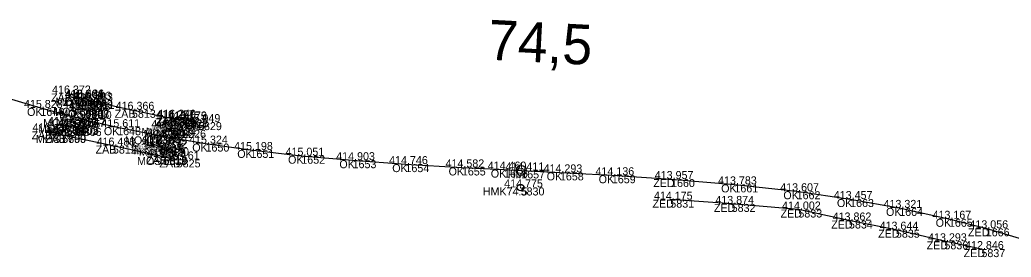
# Model space of a CAD drawing. Extents: x -621782 to -610392, y -1141853 to -1122321.
# Drawn here: x -619315.9 to -619167.3, y -1130096 to -1130060.4 of the extents above; entities that cross this region are included whole.
import ezdxf

# ---------------------------------------------------------------- set-up
doc = ezdxf.new("R2010")
doc.units = 0
for name, color, linetype in [('Vrstva 1', 7, 'Continuous'), ('Vrstva 13', 7, 'Continuous'), ('Vrstva 17', 7, 'Continuous'), ('Vrstva 18', 7, 'Continuous'), ('Vrstva 60', 7, 'Continuous'), ('Vrstva 61', 7, 'Continuous'), ('Vrstva 62', 7, 'Continuous'), ('Vrstva 7', 7, 'Continuous')]:
    doc.layers.add(name, color=color, linetype=linetype)

msp = doc.modelspace()

# ---------------------------------------------------------------- linework, layer by layer
at = {"layer": 'Vrstva 1'}
msp.add_lwpolyline([(-619320.09, -1130071.43), (-619312.85, -1130073.62), (-619306.69, -1130075.26), (-619301.33, -1130076.51), (-619294.43, -1130077.88), (-619288.08, -1130078.97), (-619281.34, -1130079.93), (-619273.72, -1130080.79), (-619266.03, -1130081.46), (-619258.1, -1130082.05), (-619249.64, -1130082.54), (-619243.32, -1130082.87), (-619240.74, -1130083), (-619234.94, -1130083.29), (-619227.15, -1130083.72), (-619218.27, -1130084.29), (-619208.77, -1130085.09), (-619199.44, -1130086.12), (-619191.42, -1130087.29), (-619184.06, -1130088.62), (-619176.61, -1130090.25), (-619171.08, -1130091.68), (-619164.55, -1130093.59)], dxfattribs=at)
at = {"layer": 'Vrstva 13'}
msp.add_lwpolyline([(-619171.73, -1130094.8), (-619177.28, -1130093.63), (-619184.55, -1130091.89), (-619191.59, -1130090.51), (-619199.18, -1130088.86), (-619209.18, -1130088.02), (-619218.38, -1130087.38)], dxfattribs=at)
at = {"layer": 'Vrstva 17'}
for points in [[(-619308.64, -1130071.46), (-619306.75, -1130072.12), (-619305.54, -1130072.39), (-619305.32, -1130072.57), (-619299.11, -1130073.9), (-619293.05, -1130075.18), (-619292.86, -1130075.09), (-619291.25, -1130075.42), (-619289.21, -1130075.75)], [(-619311.57, -1130077.13), (-619309.55, -1130077.66), (-619301.97, -1130079.27), (-619294.38, -1130080.89), (-619292.4, -1130081.34)]]:
    msp.add_lwpolyline(points, dxfattribs=at)
at = {"layer": 'Vrstva 18'}
for points in [[(-619309.59, -1130077.66), (-619309.26, -1130076.16), (-619307.78, -1130076.49), (-619307.65, -1130076.36), (-619307.23, -1130076.63), (-619305.73, -1130074.07), (-619306.1, -1130073.97), (-619306.07, -1130073.84), (-619306.98, -1130073.6), (-619306.65, -1130072.06)], [(-619294.4, -1130080.99), (-619294.13, -1130079.59), (-619294.94, -1130079.39), (-619294.83, -1130079.17), (-619295.25, -1130078.93), (-619293.76, -1130076.64), (-619293.36, -1130076.93), (-619293.09, -1130076.58), (-619291.58, -1130076.9), (-619291.22, -1130075.34)]]:
    msp.add_lwpolyline(points, dxfattribs=at)
at = {"layer": 'Vrstva 60'}
for p, q in [((-619308.64, -1130071.46), (-619308.64, -1130071.46)), ((-619306.75, -1130072.12), (-619306.75, -1130072.12)), ((-619306.65, -1130072.06), (-619306.65, -1130072.06)), ((-619305.54, -1130072.39), (-619305.54, -1130072.39)), ((-619312.85, -1130073.62), (-619312.85, -1130073.62)), ((-619306.98, -1130073.6), (-619306.98, -1130073.6)), ((-619306.07, -1130073.84), (-619306.07, -1130073.84)), ((-619305.32, -1130072.57), (-619305.32, -1130072.57)), ((-619299.11, -1130073.9), (-619299.11, -1130073.9)), ((-619306.69, -1130075.26), (-619306.69, -1130075.26)), ((-619306.1, -1130073.97), (-619306.1, -1130073.97)), ((-619305.73, -1130074.07), (-619305.73, -1130074.07)), ((-619293.05, -1130075.18), (-619293.05, -1130075.18)), ((-619292.86, -1130075.09), (-619292.86, -1130075.09)), ((-619291.22, -1130075.34), (-619291.22, -1130075.34)), ((-619309.26, -1130076.16), (-619309.26, -1130076.16)), ((-619307.78, -1130076.49), (-619307.78, -1130076.49)), ((-619307.65, -1130076.36), (-619307.65, -1130076.36)), ((-619307.23, -1130076.63), (-619307.23, -1130076.63)), ((-619301.33, -1130076.51), (-619301.33, -1130076.51)), ((-619293.76, -1130076.64), (-619293.76, -1130076.64)), ((-619293.09, -1130076.58), (-619293.09, -1130076.58)), ((-619291.25, -1130075.42), (-619291.25, -1130075.42)), ((-619289.21, -1130075.75), (-619289.21, -1130075.75)), ((-619311.57, -1130077.13), (-619311.57, -1130077.13)), ((-619309.59, -1130077.66), (-619309.59, -1130077.66)), ((-619309.55, -1130077.66), (-619309.55, -1130077.66)), ((-619294.43, -1130077.88), (-619294.43, -1130077.88)), ((-619293.36, -1130076.93), (-619293.36, -1130076.93)), ((-619291.58, -1130076.9), (-619291.58, -1130076.9)), ((-619301.97, -1130079.27), (-619301.97, -1130079.27)), ((-619295.25, -1130078.93), (-619295.25, -1130078.93)), ((-619294.94, -1130079.39), (-619294.94, -1130079.39)), ((-619294.83, -1130079.17), (-619294.83, -1130079.17)), ((-619294.13, -1130079.59), (-619294.13, -1130079.59)), ((-619288.08, -1130078.97), (-619288.08, -1130078.97)), ((-619294.4, -1130080.99), (-619294.4, -1130080.99)), ((-619294.38, -1130080.89), (-619294.38, -1130080.89)), ((-619292.4, -1130081.34), (-619292.4, -1130081.34)), ((-619281.34, -1130079.93), (-619281.34, -1130079.93)), ((-619273.72, -1130080.79), (-619273.72, -1130080.79)), ((-619266.03, -1130081.46), (-619266.03, -1130081.46)), ((-619258.1, -1130082.05), (-619258.1, -1130082.05)), ((-619249.64, -1130082.54), (-619249.64, -1130082.54)), ((-619243.32, -1130082.87), (-619243.32, -1130082.87)), ((-619240.74, -1130083), (-619240.74, -1130083)), ((-619234.94, -1130083.29), (-619234.94, -1130083.29)), ((-619227.15, -1130083.72), (-619227.15, -1130083.72)), ((-619218.27, -1130084.29), (-619218.27, -1130084.29)), ((-619240.83, -1130085.55), (-619240.83, -1130085.55)), ((-619208.77, -1130085.09), (-619208.77, -1130085.09)), ((-619199.44, -1130086.12), (-619199.44, -1130086.12)), ((-619191.42, -1130087.29), (-619191.42, -1130087.29)), ((-619218.38, -1130087.38), (-619218.38, -1130087.38)), ((-619209.18, -1130088.02), (-619209.18, -1130088.02)), ((-619184.06, -1130088.62), (-619184.06, -1130088.62)), ((-619199.18, -1130088.86), (-619199.18, -1130088.86)), ((-619176.61, -1130090.25), (-619176.61, -1130090.25)), ((-619191.59, -1130090.51), (-619191.59, -1130090.51)), ((-619171.08, -1130091.68), (-619171.08, -1130091.68)), ((-619184.55, -1130091.89), (-619184.55, -1130091.89)), ((-619177.28, -1130093.63), (-619177.28, -1130093.63)), ((-619171.73, -1130094.8), (-619171.73, -1130094.8))]:
    msp.add_line(p, q, dxfattribs=at)
at = {"layer": 'Vrstva 7'}
msp.add_line((-619240.88, -1130085.55), (-619240.78, -1130085.55), dxfattribs=at)
for centre, radius in [((-619240.74, -1130083), 0.75), ((-619240.83, -1130085.55), 0.5)]:
    msp.add_circle(centre, radius, dxfattribs=at)

# ---------------------------------------------------------------- texts
at = {"layer": 'Vrstva 60'}
for s, p in [('5797', (-619308.64, -1130072.66)), ('5801', (-619306.75, -1130073.32)), ('5803', (-619306.65, -1130073.26)), ('5809', (-619305.54, -1130073.59)), ('1646', (-619312.85, -1130074.82)), ('5804', (-619306.98, -1130074.8)), ('5807', (-619306.07, -1130075.04)), ('5811', (-619305.32, -1130073.77)), ('5813', (-619299.11, -1130075.1)), ('1647', (-619306.69, -1130076.46)), ('5808', (-619306.1, -1130075.17)), ('5810', (-619305.73, -1130075.27)), ('5821', (-619293.05, -1130076.38)), ('5823', (-619292.86, -1130076.29)), ('5827', (-619291.25, -1130076.62)), ('5828', (-619291.22, -1130076.54)), ('5798', (-619309.26, -1130077.36)), ('5802', (-619307.78, -1130077.69)), ('5805', (-619307.65, -1130077.56)), ('5806', (-619307.23, -1130077.83)), ('1648', (-619301.33, -1130077.71)), ('5817', (-619293.76, -1130077.84)), ('5824', (-619293.09, -1130077.78)), ('5826', (-619291.58, -1130078.1)), ('5829', (-619289.21, -1130076.95)), ('5796', (-619311.57, -1130078.33)), ('5799', (-619309.59, -1130078.86)), ('5800', (-619309.55, -1130078.86)), ('1649', (-619294.43, -1130079.08)), ('5822', (-619293.36, -1130078.13)), ('5812', (-619301.97, -1130080.47)), ('5814', (-619295.25, -1130080.13)), ('5815', (-619294.94, -1130080.59)), ('5816', (-619294.83, -1130080.37)), ('5820', (-619294.13, -1130080.79)), ('1650', (-619288.08, -1130080.17)), ('5819', (-619294.4, -1130082.19)), ('5818', (-619294.38, -1130082.08)), ('5825', (-619292.4, -1130082.54)), ('1651', (-619281.34, -1130081.12)), ('1652', (-619273.72, -1130081.99)), ('1653', (-619266.03, -1130082.66)), ('1654', (-619258.1, -1130083.25)), ('1655', (-619249.64, -1130083.75)), ('1656', (-619243.32, -1130084.07)), ('1657', (-619240.74, -1130084.2)), ('1658', (-619234.94, -1130084.49)), ('1659', (-619227.15, -1130084.92)), ('1660', (-619218.27, -1130085.49)), ('5830', (-619240.83, -1130086.75)), ('1661', (-619208.77, -1130086.29)), ('1662', (-619199.44, -1130087.32)), ('1663', (-619191.42, -1130088.49)), ('5831', (-619218.38, -1130088.58)), ('5832', (-619209.18, -1130089.22)), ('1664', (-619184.06, -1130089.82)), ('5833', (-619199.18, -1130090.06)), ('1665', (-619176.61, -1130091.45)), ('5834', (-619191.59, -1130091.71)), ('1666', (-619171.08, -1130092.88)), ('5835', (-619184.55, -1130093.09)), ('5836', (-619177.28, -1130094.83)), ('5837', (-619171.73, -1130096))]:
    msp.add_text(s, height=1.2, dxfattribs=at).set_placement(p)
at = {"layer": 'Vrstva 61'}
for s, p in [('416.372', (-619311.09, -1130071.46)), ('416.504', (-619309.2, -1130072.12)), ('415.486', (-619309.1, -1130072.06)), ('415.828', (-619315.31, -1130073.62)), ('415.490', (-619309.44, -1130073.6)), ('416.503', (-619307.99, -1130072.39)), ('416.483', (-619307.77, -1130072.57)), ('415.505', (-619308.55, -1130073.97)), ('415.500', (-619308.52, -1130073.84)), ('415.515', (-619308.19, -1130074.07)), ('416.366', (-619301.56, -1130073.9)), ('416.249', (-619295.31, -1130075.09)), ('415.650', (-619311.71, -1130076.16)), ('415.647', (-619310.23, -1130076.49)), ('415.656', (-619310.1, -1130076.36)), ('415.719', (-619309.15, -1130075.26)), ('415.611', (-619303.69, -1130076.51)), ('415.273', (-619295.54, -1130076.58)), ('416.257', (-619295.5, -1130075.18)), ('416.175', (-619293.71, -1130075.42)), ('415.179', (-619293.67, -1130075.34)), ('415.949', (-619291.66, -1130075.75)), ('416.416', (-619314.02, -1130077.13)), ('415.633', (-619312.04, -1130077.66)), ('416.655', (-619312.01, -1130077.66)), ('415.645', (-619309.69, -1130076.63)), ('415.470', (-619296.88, -1130077.88)), ('415.288', (-619296.21, -1130076.64)), ('415.276', (-619295.81, -1130076.93)), ('415.203', (-619294.03, -1130076.9)), ('416.483', (-619304.42, -1130079.27)), ('415.366', (-619297.7, -1130078.93)), ('415.373', (-619297.39, -1130079.39)), ('415.372', (-619297.28, -1130079.17)), ('415.372', (-619296.58, -1130079.59)), ('415.324', (-619290.54, -1130078.97)), ('415.352', (-619296.85, -1130080.99)), ('416.335', (-619296.84, -1130080.89)), ('415.198', (-619283.79, -1130079.93)), ('415.051', (-619276.08, -1130080.79)), ('416.161', (-619294.76, -1130081.34)), ('414.903', (-619268.48, -1130081.46)), ('414.746', (-619260.55, -1130082.05)), ('414.582', (-619252.09, -1130082.54)), ('414.460', (-619245.77, -1130082.87)), ('414.411', (-619243.09, -1130083)), ('414.293', (-619237.39, -1130083.29)), ('414.136', (-619229.6, -1130083.72)), ('413.957', (-619220.72, -1130084.29)), ('413.783', (-619211.22, -1130085.09)), ('414.775', (-619243.29, -1130085.55)), ('413.607', (-619201.9, -1130086.12)), ('414.175', (-619220.84, -1130087.38)), ('413.874', (-619211.63, -1130088.02)), ('413.457', (-619193.87, -1130087.29)), ('414.002', (-619201.63, -1130088.86)), ('413.321', (-619186.41, -1130088.62)), ('413.862', (-619194.04, -1130090.51)), ('413.167', (-619179.06, -1130090.25)), ('413.644', (-619187, -1130091.89)), ('413.056', (-619173.53, -1130091.68)), ('413.293', (-619179.73, -1130093.63)), ('412.846', (-619174.18, -1130094.8))]:
    msp.add_text(s, height=1.2, dxfattribs=at).set_placement(p)
at = {"layer": 'Vrstva 62'}
for s, p in [('ZAB', (-619311.24, -1130072.66)), ('MOST', (-619310.59, -1130073.26)), ('ZAB', (-619309.35, -1130073.32)), ('ZAB', (-619308.14, -1130073.59)), ('OK', (-619314.84, -1130074.82)), ('MOST', (-619310.93, -1130074.8)), ('MOST', (-619310.01, -1130075.04)), ('ZAB', (-619307.92, -1130073.77)), ('ZAB', (-619301.71, -1130075.1)), ('MOSTBS', (-619312.43, -1130076.46)), ('MOST', (-619310.04, -1130075.17)), ('MOST', (-619309.68, -1130075.27)), ('ZAB', (-619295.65, -1130076.38)), ('ZAB', (-619295.46, -1130076.29)), ('MOST', (-619295.16, -1130076.54)), ('MOST', (-619313.2, -1130077.36)), ('MOST', (-619311.73, -1130077.69)), ('MOST', (-619311.59, -1130077.56)), ('MOST', (-619311.18, -1130077.83)), ('OK', (-619303.32, -1130077.71)), ('MOST', (-619297.7, -1130077.84)), ('MOST', (-619297.04, -1130077.78)), ('MOST', (-619295.53, -1130078.1)), ('ZAB', (-619293.85, -1130076.62)), ('ZAB', (-619291.81, -1130076.95)), ('ZAB', (-619314.17, -1130078.33)), ('MOST', (-619313.53, -1130078.86)), ('ZAB', (-619312.15, -1130078.86)), ('MOSTBS', (-619300.16, -1130079.08)), ('MOST', (-619297.3, -1130078.13)), ('ZAB', (-619304.57, -1130080.47)), ('MOST', (-619299.19, -1130080.13)), ('MOST', (-619298.89, -1130080.59)), ('MOST', (-619298.78, -1130080.37)), ('MOST', (-619298.08, -1130080.79)), ('OK', (-619290.07, -1130080.17)), ('MOST', (-619298.35, -1130082.19)), ('ZAB', (-619296.98, -1130082.08)), ('ZAB', (-619295, -1130082.54)), ('OK', (-619283.32, -1130081.12)), ('OK', (-619275.7, -1130081.99)), ('OK', (-619268.01, -1130082.66)), ('OK', (-619260.08, -1130083.25)), ('OK', (-619251.63, -1130083.75)), ('OK', (-619245.3, -1130084.07)), ('HM', (-619242.77, -1130084.2)), ('OK', (-619236.92, -1130084.49)), ('OK', (-619229.13, -1130084.92)), ('ZED', (-619220.94, -1130085.49)), ('HMK74.5', (-619246.5, -1130086.75)), ('OK', (-619210.76, -1130086.29)), ('OK', (-619201.43, -1130087.32)), ('OK', (-619193.4, -1130088.49)), ('ZED', (-619221.06, -1130088.58)), ('ZED', (-619211.85, -1130089.22)), ('OK', (-619186.04, -1130089.82)), ('ZED', (-619201.86, -1130090.06)), ('OK', (-619178.59, -1130091.45)), ('ZED', (-619194.26, -1130091.71)), ('ZED', (-619173.75, -1130092.88)), ('ZED', (-619187.22, -1130093.09)), ('ZED', (-619179.95, -1130094.83)), ('ZED', (-619174.4, -1130096))]:
    msp.add_text(s, height=1.2, dxfattribs=at).set_placement(p)
at = {"layer": 'Vrstva 7'}
msp.add_text('74,5', height=6, rotation=357.0395, dxfattribs=at).set_placement((-619245.82, -1130066.37))

doc.saveas('drawing.dxf')
